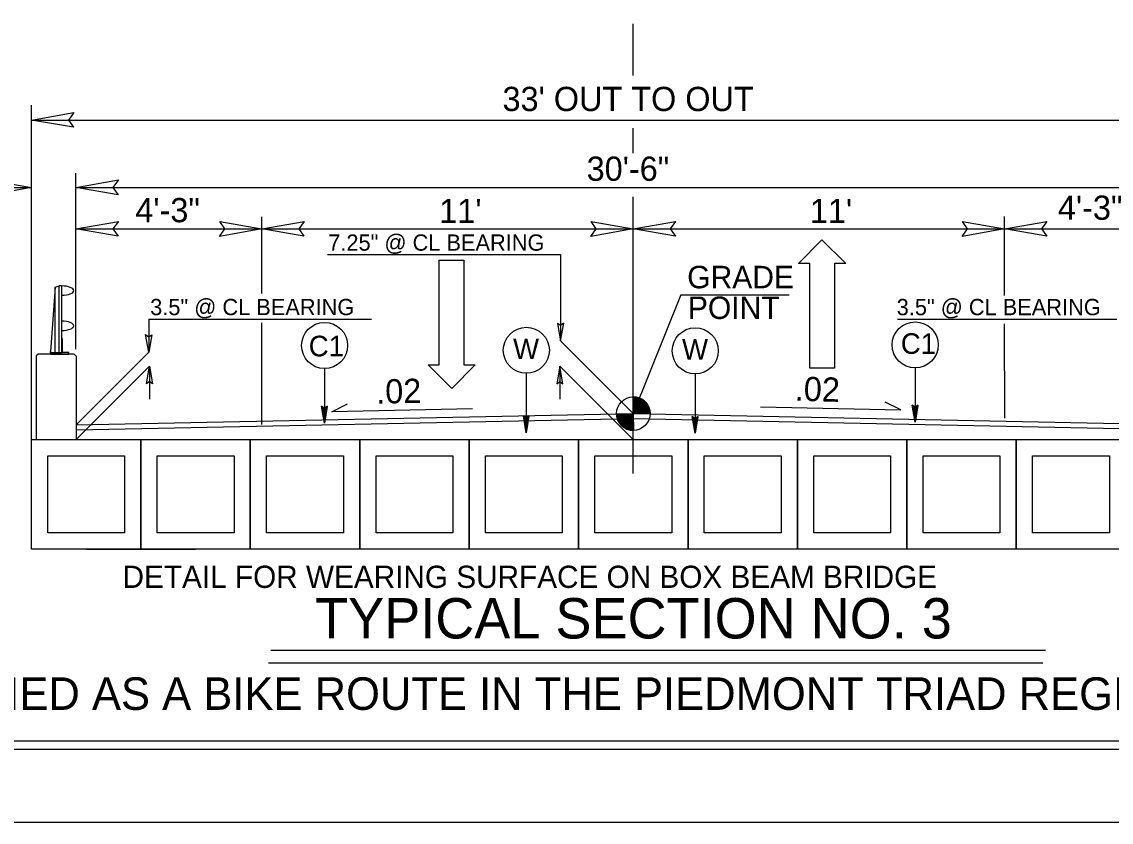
# Model space of a CAD drawing. Extents: x 55823 to 57507, y 47399 to 48499.
# Drawn here: x 56414.9 to 56749.5, y 47399.4 to 47645.4 of the extents above; entities that cross this region are included whole.
import ezdxf

# ---------------------------------------------------------------- set-up
doc = ezdxf.new("R2010")
doc.units = 0
for name, color, linetype in [('Old_Level_1', 7, 'Continuous'), ('Old_Level_11', 7, 'Continuous'), ('Old_Level_2', 7, 'Continuous'), ('Old_Level_20', 7, 'Continuous'), ('Old_Level_28', 7, 'Continuous'), ('Prop Lane Arrow CELL', 7, 'Continuous'), ('Sheet Plot Border Inside CELL', 7, 'Continuous'), ('Sheet Plot Border Outside CELL', 7, 'Continuous'), ('Sheet Typical CELL', 7, 'Continuous'), ('Typical Bridge Rail Two Bar CELL', 7, 'Continuous'), ('Typical Grade Point Symbol CELL', 7, 'Continuous'), ('Typical Terminator CELL', 7, 'Continuous'), ('Typical Text General CELL', 7, 'Continuous')]:
    doc.layers.add(name, color=color, linetype=linetype)

msp = doc.modelspace()

# ---------------------------------------------------------------- linework, layer by layer
at = {"layer": 'Old_Level_1'}
for p, q in [((56602.72, 47506.56), (56602.68, 47591.56)), ((56488.65, 47561.81), (56488.64, 47585.4)), ((56716.74, 47561.27), (56716.73, 47585.49)), ((56488.67, 47521.6), (56488.65, 47552.85)), ((56716.76, 47523.54), (56716.75, 47552.57)), ((56689.28, 47522.37), (56688.37, 47527.55)), ((56689.28, 47526.88), (56688.37, 47527.55)), ((56689.28, 47522.37), (56690.2, 47527.55)), ((56690.2, 47527.55), (56689.28, 47526.88)), ((56507.92, 47522.02), (56507, 47527.2)), ((56507.92, 47526.52), (56507, 47527.2)), ((56507.92, 47522.02), (56507.13, 47527.1)), ((56507.26, 47527), (56507.92, 47522.02)), ((56507.92, 47522.02), (56507.4, 47526.91)), ((56507.53, 47526.81), (56507.92, 47522.02)), ((56507.92, 47522.02), (56507.66, 47526.72)), ((56507.79, 47526.62), (56507.92, 47522.02)), ((56507.92, 47522.02), (56508.83, 47527.2)), ((56508.83, 47527.2), (56507.92, 47526.52)), ((56508.7, 47527.1), (56507.92, 47522.02)), ((56507.92, 47522.02), (56508.57, 47527)), ((56508.44, 47526.91), (56507.92, 47522.02)), ((56507.92, 47522.02), (56508.31, 47526.81)), ((56508.18, 47526.72), (56507.92, 47522.02)), ((56507.92, 47522.02), (56508.05, 47526.62)), ((56507.92, 47526.52), (56507.92, 47522.02)), ((56569.87, 47519.06), (56568.96, 47524.25)), ((56569.87, 47523.57), (56568.96, 47524.25)), ((56569.87, 47519.06), (56570.79, 47524.25)), ((56570.79, 47524.25), (56569.87, 47523.57)), ((56689.28, 47522.37), (56688.5, 47527.45)), ((56688.63, 47527.36), (56689.28, 47522.37)), ((56689.28, 47522.37), (56688.76, 47527.26)), ((56688.89, 47527.17), (56689.28, 47522.37)), ((56689.28, 47522.37), (56689.02, 47527.07)), ((56689.15, 47526.98), (56689.28, 47522.37)), ((56690.06, 47527.45), (56689.28, 47522.37)), ((56689.28, 47522.37), (56689.93, 47527.36)), ((56689.8, 47527.26), (56689.28, 47522.37)), ((56689.28, 47522.37), (56689.67, 47527.17)), ((56689.54, 47527.07), (56689.28, 47522.37)), ((56689.28, 47522.37), (56689.41, 47526.98)), ((56689.28, 47526.88), (56689.28, 47522.37)), ((56569.87, 47519.06), (56569.09, 47524.15)), ((56569.22, 47524.05), (56569.87, 47519.06)), ((56569.87, 47519.06), (56569.35, 47523.96)), ((56569.48, 47523.86), (56569.87, 47519.06)), ((56569.87, 47519.06), (56569.61, 47523.77)), ((56569.74, 47523.67), (56569.87, 47519.06)), ((56570.65, 47524.15), (56569.87, 47519.06)), ((56569.87, 47519.06), (56570.52, 47524.05)), ((56570.39, 47523.96), (56569.87, 47519.06)), ((56569.87, 47519.06), (56570.26, 47523.86)), ((56570.13, 47523.77), (56569.87, 47519.06)), ((56569.87, 47519.06), (56570, 47523.67)), ((56569.87, 47523.57), (56569.87, 47519.06)), ((56621.75, 47518.89), (56620.84, 47524.08)), ((56621.75, 47523.4), (56620.84, 47524.08)), ((56621.75, 47518.89), (56620.97, 47523.98)), ((56621.1, 47523.88), (56621.75, 47518.89)), ((56621.75, 47518.89), (56621.23, 47523.79)), ((56621.36, 47523.69), (56621.75, 47518.89)), ((56621.75, 47518.89), (56621.49, 47523.6)), ((56621.62, 47523.5), (56621.75, 47518.89)), ((56621.75, 47518.89), (56622.67, 47524.08)), ((56622.67, 47524.08), (56621.75, 47523.4)), ((56622.53, 47523.98), (56621.75, 47518.89)), ((56621.75, 47518.89), (56622.4, 47523.88)), ((56622.27, 47523.79), (56621.75, 47518.89)), ((56621.75, 47518.89), (56622.14, 47523.69)), ((56622.01, 47523.6), (56621.75, 47518.89)), ((56621.75, 47518.89), (56621.88, 47523.5)), ((56621.75, 47523.4), (56621.75, 47518.89)), ((56491.46, 47452.3), (56729.29, 47452.3)), ((56490.68, 47448.37), (56728.5, 47448.37))]:
    msp.add_line(p, q, dxfattribs=at)
at = {"layer": 'Old_Level_11'}
for p, q in [((56417.91, 47615.15), (56787.52, 47615.15)), ((56431.58, 47594.45), (56773.49, 47594.45))]:
    msp.add_line(p, q, dxfattribs=at)
at = {"layer": 'Old_Level_2'}
for p, q in [((56507.92, 47538.8), (56507.92, 47522.02)), ((56689.28, 47539), (56689.28, 47522.37)), ((56569.87, 47537.33), (56569.87, 47519.07)), ((56621.75, 47537.16), (56621.75, 47518.89))]:
    msp.add_line(p, q, dxfattribs=at)
for centre in [(56507.92, 47545.87), (56569.87, 47544.4), (56621.75, 47544.23), (56689.28, 47546.07)]:
    msp.add_circle(centre, 7.07, dxfattribs=at)
at = {"layer": 'Old_Level_28'}
for p, q in [((56602.67, 47628.86), (56602.66, 47644.73)), ((56417.91, 47516.98), (56417.91, 47619.77)), ((56602.68, 47604.95), (56602.68, 47612.62)), ((56431.58, 47544.79), (56431.58, 47598.86)), ((56385.38, 47594.37), (56417.91, 47594.41)), ((56431.58, 47581.71), (56488.64, 47581.71)), ((56488.64, 47581.71), (56602.69, 47581.71)), ((56602.69, 47581.71), (56716.74, 47581.71)), ((56716.74, 47581.71), (56773.49, 47581.71)), ((56617.33, 47561.41), (56602.71, 47524.95)), ((56617.33, 47561.41), (56650.59, 47561.41)), ((56510.18, 47525.51), (56514.97, 47527.91)), ((56684.85, 47526.1), (56680.07, 47528.5)), ((56431.61, 47521.48), (56602.71, 47524.95)), ((56553.31, 47526.42), (56510.18, 47525.51)), ((56602.71, 47524.95), (56773.52, 47521.48)), ((56641.73, 47527), (56684.85, 47526.1)), ((56431.61, 47519.98), (56602.68, 47523.45)), ((56602.68, 47523.45), (56773.49, 47519.98)), ((56417.91, 47516.98), (56451.51, 47516.98)), ((56434.71, 47483.28), (56468.31, 47483.28))]:
    msp.add_line(p, q, dxfattribs=at)
for points in [[(56430.85, 47612.92), (56417.91, 47615.15), (56430.92, 47617.45), (56429.27, 47615.15)], [(56404.98, 47596.64), (56417.91, 47594.41), (56404.9, 47592.11), (56406.56, 47594.41)], [(56444.52, 47592.22), (56431.58, 47594.45), (56444.59, 47596.75), (56442.93, 47594.45)], [(56444.52, 47579.48), (56431.58, 47581.71), (56444.59, 47584.01), (56442.93, 47581.71)], [(56475.71, 47583.94), (56488.64, 47581.71), (56475.63, 47579.41), (56477.29, 47581.71)], [(56501.58, 47579.48), (56488.64, 47581.71), (56501.65, 47584.01), (56500, 47581.71)], [(56589.75, 47583.94), (56602.69, 47581.71), (56589.68, 47579.41), (56591.33, 47581.71)], [(56615.63, 47579.48), (56602.69, 47581.71), (56615.7, 47584.01), (56614.04, 47581.71)], [(56703.8, 47583.94), (56716.74, 47581.71), (56703.73, 47579.41), (56705.38, 47581.71)], [(56729.67, 47579.48), (56716.74, 47581.71), (56729.74, 47584.01), (56728.09, 47581.71)], [(56417.91, 47516.98), (56451.51, 47516.98), (56451.51, 47483.28), (56417.91, 47483.28)], [(56451.51, 47516.98), (56485.11, 47516.98), (56485.11, 47483.28), (56451.51, 47483.28)], [(56485.11, 47516.98), (56518.71, 47516.98), (56518.71, 47483.28), (56485.11, 47483.28)], [(56518.71, 47516.98), (56552.31, 47516.98), (56552.31, 47483.28), (56518.71, 47483.28)], [(56552.31, 47516.98), (56585.92, 47516.98), (56585.92, 47483.28), (56552.31, 47483.28)], [(56585.92, 47516.98), (56619.52, 47516.98), (56619.52, 47483.28), (56585.92, 47483.28)], [(56619.52, 47516.98), (56653.12, 47516.98), (56653.12, 47483.28), (56619.52, 47483.28)], [(56653.12, 47516.98), (56686.72, 47516.98), (56686.72, 47483.28), (56653.12, 47483.28)], [(56686.72, 47516.98), (56720.32, 47516.98), (56720.32, 47483.28), (56686.72, 47483.28)], [(56720.32, 47516.98), (56753.92, 47516.98), (56753.92, 47483.28), (56720.32, 47483.28)], [(56422.91, 47511.98), (56446.51, 47511.98), (56446.51, 47488.28), (56422.91, 47488.28)], [(56480.11, 47511.98), (56480.11, 47488.28), (56456.51, 47488.28), (56456.51, 47511.98)], [(56490.11, 47511.98), (56513.71, 47511.98), (56513.71, 47488.28), (56490.11, 47488.28)], [(56523.71, 47511.98), (56547.31, 47511.98), (56547.31, 47488.28), (56523.71, 47488.28)], [(56557.31, 47511.98), (56580.92, 47511.98), (56580.92, 47488.28), (56557.31, 47488.28)], [(56590.92, 47511.98), (56614.52, 47511.98), (56614.52, 47488.28), (56590.92, 47488.28)], [(56624.52, 47511.98), (56648.12, 47511.98), (56648.12, 47488.28), (56624.52, 47488.28)], [(56658.12, 47511.98), (56681.72, 47511.98), (56681.72, 47488.28), (56658.12, 47488.28)], [(56691.72, 47511.98), (56715.32, 47511.98), (56715.32, 47488.28), (56691.72, 47488.28)], [(56748.92, 47511.98), (56748.92, 47488.28), (56725.32, 47488.28), (56725.32, 47511.98)]]:
    msp.add_lwpolyline(points, close=True, dxfattribs=at)
at = {"layer": 'Prop Lane Arrow CELL'}
for p, q in [((56653.49, 47571.11), (56660.62, 47578.36)), ((56660.62, 47578.36), (56667.98, 47571.11)), ((56543.13, 47539.95), (56543.13, 47572.15)), ((56543.13, 47572.15), (56550.72, 47572.15)), ((56550.72, 47572.15), (56550.72, 47539.95)), ((56656.94, 47571.11), (56653.49, 47571.11)), ((56656.94, 47538.92), (56656.94, 47571.11)), ((56667.98, 47571.11), (56664.53, 47571.11)), ((56664.53, 47571.11), (56664.53, 47538.92)), ((56547.04, 47532.7), (56539.68, 47539.95)), ((56539.68, 47539.95), (56543.13, 47539.95)), ((56554.17, 47539.95), (56547.04, 47532.7)), ((56550.72, 47539.95), (56554.17, 47539.95)), ((56664.53, 47538.92), (56656.94, 47538.92))]:
    msp.add_line(p, q, dxfattribs=at)
at = {"layer": 'Sheet Plot Border Inside CELL'}
msp.add_lwpolyline([(57502.66, 48476.93), (55836.16, 48476.93), (55836.16, 47421.83), (57502.66, 47421.83)], close=True, dxfattribs=at)
at = {"layer": 'Sheet Plot Border Outside CELL'}
msp.add_lwpolyline([(57507.16, 48499.38), (55823.16, 48499.38), (55823.16, 47399.38), (57507.16, 47399.38)], close=True, dxfattribs=at)
at = {"layer": 'Sheet Typical CELL'}
msp.add_lwpolyline([(57490.16, 48474.38), (55990.16, 48474.38), (55990.16, 47424.38), (57490.16, 47424.38)], close=True, dxfattribs=at)
at = {"layer": 'Typical Bridge Rail Two Bar CELL'}
for p, q in [((56425.17, 47563.79), (56423.73, 47544)), ((56425.17, 47563.79), (56426.42, 47564.2)), ((56425.17, 47543.59), (56425.17, 47563.79)), ((56427.24, 47564.2), (56426.42, 47564.2)), ((56426.42, 47543.59), (56426.42, 47564.2)), ((56427.24, 47543.59), (56427.24, 47564.2)), ((56425.17, 47554.33), (56425.13, 47554.33)), ((56419.37, 47542.64), (56419.9, 47543.17)), ((56419.37, 47542.64), (56419.37, 47516.98)), ((56431.07, 47543.17), (56419.9, 47543.17)), ((56423.73, 47543.59), (56423.73, 47544)), ((56431.07, 47543.17), (56431.61, 47542.64)), ((56431.61, 47542.64), (56431.61, 47516.98))]:
    msp.add_line(p, q, dxfattribs=at)
msp.add_lwpolyline([(56429.35, 47543.17), (56429.35, 47543.69), (56427.45, 47543.69), (56427.45, 47547.92), (56427.24, 47547.92), (56427.24, 47543.59), (56423.83, 47543.59), (56423.83, 47543.89), (56423.73, 47543.89), (56423.73, 47543.17), (56425.38, 47543.17), (56427.04, 47543.17), (56429.35, 47543.17)], dxfattribs=at)
for centre, start_param, end_param in [((56427.24, 47562.74), 6.282787, 7.853967), ((56427.24, 47562.74), 4.712404, 6.282787), ((56427.24, 47551.93), 6.282787, 7.853967), ((56427.24, 47551.93), 4.712404, 6.282787)]:
    msp.add_ellipse(centre, major_axis=(3.66, 0), ratio=0.39036, start_param=start_param, end_param=end_param, dxfattribs=at)
at = {"layer": 'Typical Grade Point Symbol CELL'}
for p, q in [((56602.71, 47524.95), (56602.65, 47530.09)), ((56597.57, 47524.88), (56602.71, 47524.95)), ((56607.86, 47525.01), (56602.71, 47524.95)), ((56602.77, 47519.8), (56602.71, 47524.95)), ((56602.71, 47524.95), (56602.77, 47519.8))]:
    msp.add_line(p, q, dxfattribs=at)
for points in [[(56602.69, 47530.1), (56602.69, 47530.1), (56602.76, 47524.95)], [(56602.8, 47530.1), (56602.86, 47524.95)], [(56602.9, 47530.09), (56602.97, 47524.95)], [(56603, 47530.09), (56603.07, 47524.95)], [(56603.11, 47530.08), (56603.17, 47524.95)], [(56603.21, 47530.07), (56603.27, 47524.96)], [(56603.31, 47530.06), (56603.38, 47524.96)], [(56603.42, 47530.05), (56603.48, 47524.96)], [(56603.52, 47530.04), (56603.58, 47524.96)], [(56603.62, 47530.02), (56603.69, 47524.96)], [(56603.73, 47529.99), (56603.79, 47524.96)], [(56603.83, 47529.97), (56603.89, 47524.96)], [(56603.93, 47529.95), (56603.99, 47524.96)], [(56604.03, 47529.92), (56604.1, 47524.97)], [(56604.14, 47529.9), (56604.2, 47524.97)], [(56604.24, 47529.86), (56604.3, 47524.97)], [(56604.35, 47529.83), (56604.41, 47524.97)], [(56604.45, 47529.8), (56604.51, 47524.97)], [(56604.55, 47529.75), (56604.61, 47524.97)], [(56604.66, 47529.71), (56604.71, 47524.97)], [(56604.76, 47529.66), (56604.82, 47524.97)], [(56604.86, 47529.62), (56604.92, 47524.98)], [(56604.97, 47529.58), (56605.02, 47524.98)], [(56605.07, 47529.52), (56605.13, 47524.98)], [(56605.17, 47529.46), (56605.23, 47524.98)], [(56605.28, 47529.41), (56605.33, 47524.98)], [(56605.38, 47529.35), (56605.44, 47524.98)], [(56605.48, 47529.28), (56605.54, 47524.98)], [(56605.59, 47529.22), (56605.64, 47524.99)], [(56605.69, 47529.14), (56605.74, 47524.99)], [(56605.8, 47529.07), (56605.85, 47524.99)], [(56605.9, 47528.99), (56605.95, 47524.99)], [(56606, 47528.9), (56606.05, 47524.99)], [(56606.11, 47528.81), (56606.16, 47524.99)], [(56606.21, 47528.72), (56606.26, 47524.99)], [(56606.32, 47528.62), (56606.36, 47524.99)], [(56606.42, 47528.52), (56606.46, 47525)], [(56606.52, 47528.4), (56606.57, 47525)], [(56606.63, 47528.28), (56606.67, 47525)], [(56606.73, 47528.16), (56606.77, 47525)], [(56606.84, 47528.02), (56606.88, 47525)], [(56606.94, 47527.87), (56606.98, 47525)], [(56607.05, 47527.71), (56607.08, 47525)], [(56597.59, 47524.88), (56597.6, 47524.32)], [(56597.69, 47524.89), (56597.71, 47523.72)], [(56597.8, 47524.89), (56597.81, 47523.35)], [(56597.9, 47524.89), (56597.92, 47523.05)], [(56598, 47524.89), (56598.03, 47522.81)], [(56598.1, 47524.89), (56598.13, 47522.59)], [(56598.21, 47524.89), (56598.24, 47522.4)], [(56598.31, 47524.89), (56598.34, 47522.22)], [(56598.41, 47524.89), (56598.45, 47522.06)], [(56598.52, 47524.9), (56598.55, 47521.91)], [(56598.62, 47524.9), (56598.66, 47521.78)], [(56598.72, 47524.9), (56598.76, 47521.65)], [(56598.82, 47524.9), (56598.87, 47521.53)], [(56598.93, 47524.9), (56598.97, 47521.41)], [(56599.03, 47524.9), (56599.08, 47521.3)], [(56599.13, 47524.9), (56599.18, 47521.2)], [(56599.24, 47524.9), (56599.28, 47521.11)], [(56599.34, 47524.91), (56599.39, 47521.02)], [(56599.44, 47524.91), (56599.49, 47520.93)], [(56599.55, 47524.91), (56599.6, 47520.85)], [(56599.65, 47524.91), (56599.7, 47520.77)], [(56599.75, 47524.91), (56599.8, 47520.7)], [(56599.85, 47524.91), (56599.91, 47520.64)], [(56599.96, 47524.91), (56600.01, 47520.57)], [(56600.06, 47524.92), (56600.12, 47520.5)], [(56600.16, 47524.92), (56600.22, 47520.44)], [(56600.27, 47524.92), (56600.32, 47520.39)], [(56600.37, 47524.92), (56600.43, 47520.33)], [(56600.47, 47524.92), (56600.53, 47520.29)], [(56600.58, 47524.92), (56600.63, 47520.24)], [(56600.68, 47524.92), (56600.74, 47520.2)], [(56600.78, 47524.92), (56600.84, 47520.16)], [(56600.88, 47524.93), (56600.94, 47520.11)], [(56600.99, 47524.93), (56601.05, 47520.08)], [(56601.09, 47524.93), (56601.15, 47520.05)], [(56601.19, 47524.93), (56601.25, 47520.01)], [(56601.3, 47524.93), (56601.36, 47519.99)], [(56601.4, 47524.93), (56601.46, 47519.96)], [(56601.5, 47524.93), (56601.56, 47519.94)], [(56601.6, 47524.93), (56601.67, 47519.91)], [(56601.71, 47524.94), (56601.77, 47519.89)], [(56601.81, 47524.94), (56601.87, 47519.87)], [(56601.91, 47524.94), (56601.98, 47519.86)], [(56602.02, 47524.94), (56602.08, 47519.84)], [(56602.12, 47524.94), (56602.18, 47519.83)], [(56602.22, 47524.94), (56602.29, 47519.82)], [(56602.32, 47524.94), (56602.39, 47519.81)], [(56602.43, 47524.94), (56602.49, 47519.81)], [(56602.53, 47524.95), (56602.6, 47519.8)], [(56602.63, 47524.95), (56602.7, 47519.8), (56602.7, 47519.8)], [(56607.15, 47527.54), (56607.18, 47525)], [(56607.26, 47527.36), (56607.29, 47525.01)], [(56607.36, 47527.15), (56607.39, 47525.01)], [(56607.47, 47526.91), (56607.49, 47525.01)], [(56607.58, 47526.62), (56607.6, 47525.01)], [(56607.68, 47526.27), (56607.7, 47525.01)], [(56607.79, 47525.74), (56607.8, 47525.01)]]:
    msp.add_lwpolyline(points, dxfattribs=at)
msp.add_circle((56602.71, 47524.95), 5.15, dxfattribs=at)
for start, end in [(0.7083, 90.7083), (180.7083, 270.7083)]:
    msp.add_arc((56602.71, 47524.95), 5.15, start, end, dxfattribs=at)
at = {"layer": 'Typical Terminator CELL'}
for points in [[(56579.46, 47552.66), (56580.39, 47547.27), (56581.35, 47552.69), (56580.39, 47552)], [(56454.85, 47549.19), (56453.93, 47543.8), (56452.97, 47549.22), (56453.93, 47548.53)], [(56453.22, 47534.13), (56454.15, 47539.52), (56455.11, 47534.1), (56454.15, 47534.79)], [(56581.11, 47534.12), (56580.18, 47539.51), (56579.23, 47534.09), (56580.18, 47534.78)]]:
    msp.add_lwpolyline(points, close=True, dxfattribs=at)
at = {"layer": 'Typical Text General CELL'}
for p, q in [((56508.85, 47573.88), (56580.39, 47573.88)), ((56580.39, 47573.88), (56580.39, 47547.27)), ((56453.93, 47553.92), (56453.93, 47543.8)), ((56453.93, 47553.92), (56522.37, 47553.92)), ((56683.84, 47553.92), (56751.2, 47553.92)), ((56602.71, 47524.95), (56580.39, 47547.27)), ((56431.61, 47521.48), (56453.93, 47543.8)), ((56431.61, 47516.98), (56454.15, 47539.52)), ((56454.15, 47539.52), (56454.15, 47529.4)), ((56580.18, 47539.51), (56580.18, 47529.39)), ((56602.72, 47516.98), (56580.18, 47539.51))]:
    msp.add_line(p, q, dxfattribs=at)

# ---------------------------------------------------------------- texts
at = {"layer": 'Old_Level_1'}
msp.add_text('TYPICAL SECTION NO. 3', height=12.4114, dxfattribs=at).set_placement((56505.02, 47455.85))
at = {"layer": 'Old_Level_11'}
for s, height, p in [("33' OUT TO OUT", 7.4468, (56562.56, 47617.92)), ('30\'-6"', 7.447, (56588.39, 47596.48))]:
    msp.add_text(s, height=height, dxfattribs=at).set_placement(p)
at = {"layer": 'Old_Level_20'}
for s, height, p in [('C1', 6.327, (56503.05, 47542.55)), ('W', 6.33, (56565.8, 47541.69)), ('W', 6.33, (56617.68, 47541.52)), ('C1', 6.327, (56684.87, 47543.31))]:
    msp.add_text(s, height=height, dxfattribs=at).set_placement(p)
at = {"layer": 'Old_Level_28'}
for s, height, p in [('4\'-3"', 7.447, (56449.8, 47583.76)), ('4\'-3"', 7.447, (56733.1, 47584.51)), ("11'", 7.447, (56543.15, 47583.5)), ("11'", 7.447, (56656.94, 47583.5)), ('7.25" @ CL BEARING', 5, (56509.05, 47575.01)), ('GRADE', 6.899, (56619.27, 47563.46)), ('POINT', 6.899, (56619.47, 47554.03)), ('3.5" @ CL BEARING', 5, (56454.37, 47555.2)), ('3.5" @ CL BEARING', 5, (56683.6, 47555.19)), ('DETAIL FOR WEARING SURFACE ON BOX BEAM BRIDGE', 6.8276, (56445.89, 47471.39)), ('SR 1767 IS IDENTIFIED AS A BIKE ROUTE IN THE PIEDMONT TRIAD REGIONAL BIKE STUDY (2005).', 10, (56286.37, 47433.91))]:
    msp.add_text(s, height=height, dxfattribs=at).set_placement(p)
for rotation, p in [(1.203, (56523.85, 47527.98)), (358.3595, (56652.22, 47528.93))]:
    msp.add_text('.02', height=7.447, rotation=rotation, dxfattribs=at).set_placement(p)

doc.saveas('drawing.dxf')
